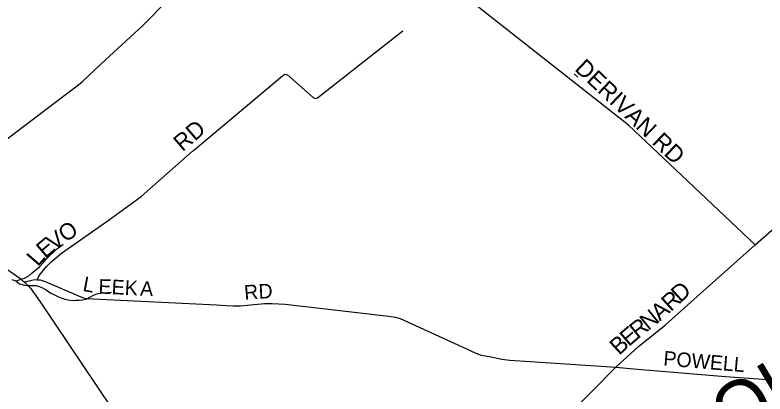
# Model space of a CAD drawing. Extents: x 0 to 784, y 0 to 440.
# Drawn here: x 82.4 to 176.2, y 72.8 to 120.2 of the extents above; entities that cross this region are included whole.
import ezdxf

# ---------------------------------------------------------------- set-up
doc = ezdxf.new("R2010")
doc.units = 0
doc.layers.add('Default', color=7, linetype='Continuous')

msp = doc.modelspace()

# ---------------------------------------------------------------- linework, layer by layer
at = {"layer": 'Default'}
for points in [[(159.093, 106.433), (128.699, 130.38), (121.403, 135.633)], [(69.807, 96.03), (75.228, 100.11), (80.359, 103.919), (88.384, 109.939), (90.368, 111.436), (90.885, 111.87), (93.161, 114.026), (97.372, 117.911), (98.273, 118.759), (101.797, 122.336)], [(125.127, 113.664), (130.904, 118.225)], [(104.638, 103.157), (104.645, 103.164), (104.75, 103.256), (115.901, 112.624), (116.17, 112.775), (116.491, 112.718), (119.704, 109.86), (119.949, 109.744), (120.259, 109.821), (125.118, 113.656), (125.127, 113.664)], [(152.755, 112.404), (152.296, 112.835)], [(147.71, 66.748), (147.721, 66.757), (148.755, 67.614), (150.74, 69.297), (151.562, 70.089), (157.528, 76.135), (160.339, 78.719), (163.742, 81.421), (167.676, 84.983), (174.947, 91.455), (179.835, 95.793), (183.569, 99.117), (183.813, 99.354), (187.916, 110.307)], [(174.947, 91.455), (165.765, 100.138), (159.093, 106.433)], [(85.202, 87.083), (85.471, 87.598), (86.365, 88.716), (86.945, 89.32), (88.248, 90.414), (94.063, 94.496), (98.209, 97.481), (104.638, 103.157)], [(63.035, 101.124), (63.172, 100.901), (63.704, 100.327), (64.468, 99.673), (66.9, 97.949), (69.807, 96.03), (70.356, 95.679), (73.131, 93.903), (78.147, 90.573), (81.809, 88.158), (83.046, 87.271), (83.611, 86.769), (83.991, 86.405), (84.356, 86.03), (85.588, 84.33), (96.319, 68.321), (103.702, 57.281), (103.922, 56.947), (104.41, 56.35), (106.182, 54.472), (106.189, 54.465)], [(82.573, 86.916), (83.152, 87.15), (83.622, 87.268), (84.168, 87.58), (84.568, 87.941), (85.559, 88.747), (85.944, 89.182), (86.272, 89.617), (86.746, 90.075), (87.234, 90.52), (87.679, 90.966), (88.048, 91.207), (88.447, 91.519)], [(82.037, 87.122), (82.563, 86.924), (83.014, 86.58), (83.627, 86.381), (84.008, 86.342), (84.521, 86.362), (85.063, 86.346), (85.458, 86.246), (85.896, 86.085), (86.347, 85.827), (86.914, 85.421), (87.381, 85.187), (87.862, 84.929), (88.285, 84.767), (88.68, 84.655), (89.089, 84.579), (89.616, 84.502), (90.012, 84.512), (90.437, 84.508), (90.877, 84.554), (91.333, 84.648), (91.775, 84.899), (92.262, 85.163), (92.674, 85.33), (93.1, 85.4), (93.584, 85.457), (94.053, 85.477), (94.509, 85.547)], [(83.611, 86.769), (84.022, 86.895), (84.541, 87.028), (84.909, 87.091), (85.202, 87.083), (85.596, 87.048), (86.19, 86.874), (90.685, 84.929), (91.003, 84.823), (91.352, 84.753), (107.604, 83.924), (108.834, 83.855), (109.698, 83.814), (110.613, 83.8), (113.638, 84.089), (114.569, 84.117), (116.181, 84.006), (129.163, 82.519), (129.927, 82.409), (130.559, 82.23), (138.759, 78.464), (140.023, 77.895), (140.709, 77.66), (141.933, 77.425), (143.295, 77.149), (144.295, 77.035), (146.803, 76.865), (157.528, 76.135)], [(157.528, 76.135), (160.244, 75.915), (171.224, 74.984), (181.099, 74.253), (188.738, 73.633)]]:
    msp.add_lwpolyline(points, dxfattribs=at)

# ---------------------------------------------------------------- texts
for s, height, rotation, p in [('DERIVAN RD', 2.1114, 316.51942, (152.267, 113.346)), ('RD', 2.0931, 40.67217, (103.37, 103.024)), ('O', 2.05, 34.94435, (88.757, 91.685)), ('V', 2.06, 36.20449, (87.32, 90.633)), ('E', 2.091, 40.35901, (86.205, 89.684)), ('L', 2.141, 48.96748, (85.3, 88.635)), ('CLINTON COUNTY', 6.72139, 30.94604, (130.501, 41.63)), ('L', 1.851, 349.28881, (90.821, 85.697)), ('E', 1.82, 357.86314, (92.847, 85.347)), ('E', 1.821, 357.16772, (94.479, 85.286)), ('K', 1.821, 357.17113, (96.118, 85.205)), ('A', 1.821, 357.16964, (98.046, 85.109)), ('R', 1.825, 4.87039, (111.146, 84.556)), ('D', 1.82, 2.68826, (112.912, 84.707)), ('D', 2.104, 42.34162, (165.594, 84.133)), ('R', 2.104, 42.33295, (164.381, 83.028)), ('A', 2.098, 41.326, (163.028, 81.837)), ('N', 2.081, 38.93599, (161.574, 80.66)), ('HIGHLAND COUNTY', 6.72139, 30.94604, (136.411, 31.572)), ('R', 2.078, 38.53462, (160.262, 79.615)), ('E', 2.092, 40.56856, (159.135, 78.65)), ('B', 2.104, 42.35474, (157.935, 77.556)), ('POWELL', 1.8249, 355.23605, (163.412, 76.368))]:
    msp.add_text(s, height=height, rotation=rotation, dxfattribs=at).set_placement(p)

doc.saveas('drawing.dxf')
